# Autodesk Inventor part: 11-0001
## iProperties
Created: 2007-02
Part Number: 11-0001
Document SubType Name: Modeling
Designer: Gilles GLEMAREC
Material: Al CU Mg 4
Author: Gilles GLEMAREC
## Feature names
1. Semelle [Extrusion]
2. Chanfreins externes [Chamfer]
3. Limitation surface de contact [Extrusion]
4. congés latéraux [Fillet]
5. congés limitation, source procédé [Fillet]
6. Bossage frontal tige glissière [Extrusion]
7. Appui mors fixe [Extrusion]
8. Ebauche glissières [Extrusion]
9. Plan extrémité glissières [Extrusion]
10. Ebauche appui glissières [Extrusion]
11. Passage mécanisme [Extrusion]
12. Dépouille primaire
13. Congé6 [Fillet]
14. Congé7 [Fillet]
15. Congé8 [Fillet]
16. nervure gauche [Mirror]
17. Dépouille secondaire
18. Dépouille interne
19. Congé9 [Fillet]
20. Congé10 [Fillet]
21. Congé11 [Fillet]
22. Congé14 [Fillet]
23. Congé12 [Fillet]
24. Congé15 [Fillet]
25. Congé16 [Fillet]
26. Congé17 [Fillet]
27. Surépaisseur inférieure [Extrusion]
28. Congé18 [Fillet]
